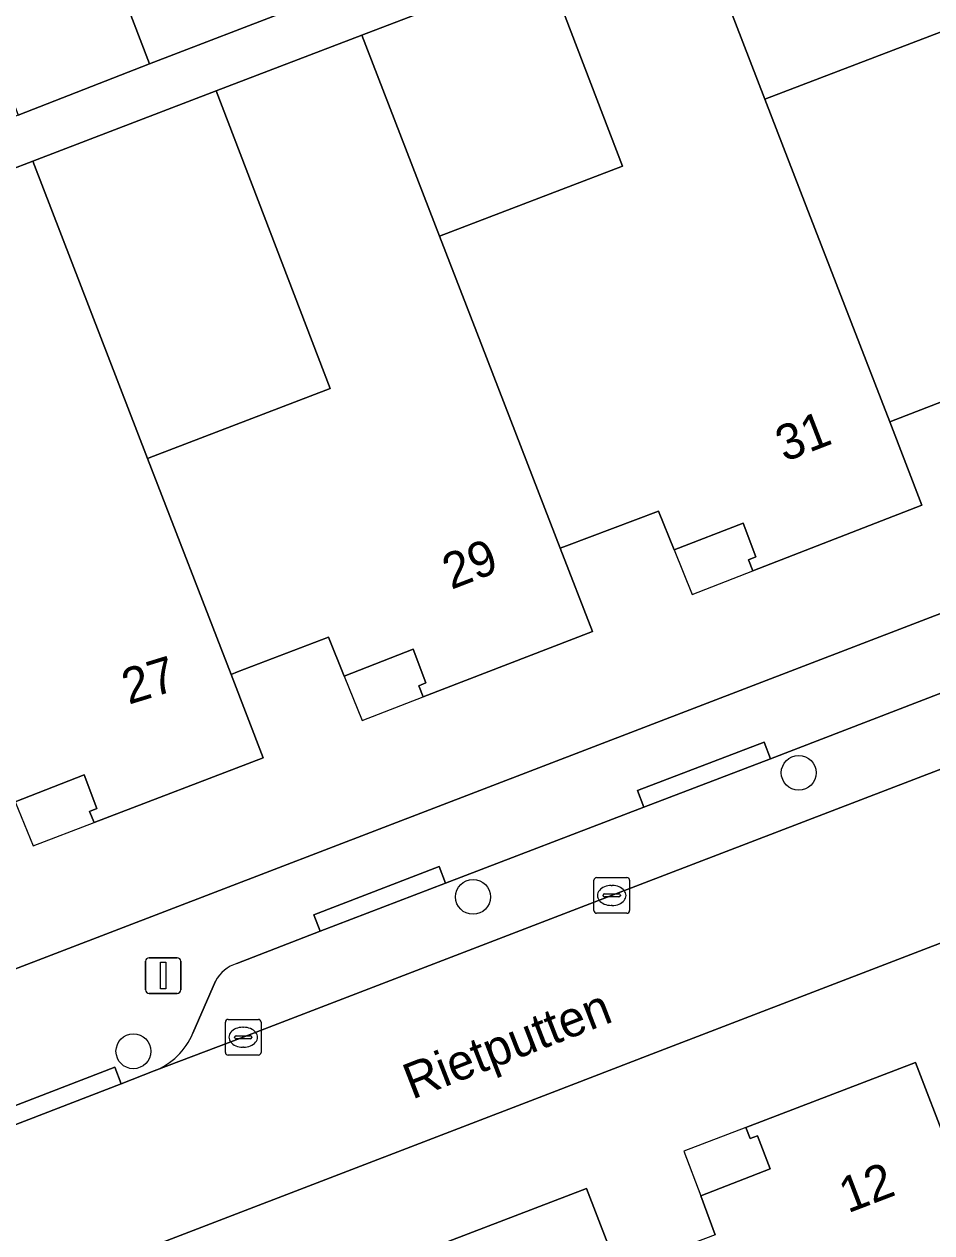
# Model space of a CAD drawing. Extents: x 159262 to 160143, y 383399 to 384319.
# Drawn here: x 159446.11 to 159471.6, y 383678.39 to 383712.34 of the extents above; entities that cross this region are included whole.
import ezdxf

# ---------------------------------------------------------------- set-up
doc = ezdxf.new("R2010")
doc.units = 0
for name, color, linetype in [('IMGEO_Boom', 7, 'Continuous'), ('IMGEO_Erf', 7, 'Continuous'), ('IMGEO_Kolk', 7, 'Continuous'), ('IMGEO_Lichtmast', 7, 'Continuous'), ('IMGEO_Openbare_ruimte_label', 7, 'Continuous'), ('IMGEO_Pand', 7, 'Continuous'), ('IMGEO_Pand_nummerreeks', 7, 'Continuous'), ('IMGEO_Pand_overbouw', 7, 'Continuous'), ('IMGEO_Parkeervlak_open', 7, 'Continuous'), ('IMGEO_Rijbaan_lokaal_open', 7, 'Continuous'), ('IMGEO_Voetpad_open', 7, 'Continuous')]:
    doc.layers.add(name, color=color, linetype=linetype)

msp = doc.modelspace()

# ---------------------------------------------------------------- linework, layer by layer
at = {"layer": 'IMGEO_Boom'}
for centre in [(159467.858, 383691.308), (159458.713, 383687.822), (159449.177, 383683.486)]:
    msp.add_circle(centre, 0.489, dxfattribs=at)
at = {"layer": 'IMGEO_Erf'}
for points in [[(159435.186, 383681.698), (159493.36, 383704.052), (159485.859, 383723.61)], [(159409.505, 383716.326), (159412.893, 383700.61), (159413.681, 383697.451), (159416.385, 383698.491), (159415.225, 383701.507), (159423.514, 383704.695), (159424.645, 383701.755), (159424.841, 383701.83), (159423.961, 383704.167), (159429.312, 383706.183), (159433.524, 383707.771), (159434.404, 383705.433), (159438.242, 383706.88), (159437.291, 383709.406), (159440.824, 383710.737), (159444.985, 383712.306), (159445.937, 383709.78), (159449.626, 383711.226), (159448.675, 383713.719)], [(159473.152, 383702.227), (159470.589, 383701.232), (159470.415, 383701.164), (159471.319, 383698.826), (159466.573, 383696.983), (159466.45, 383697.293), (159466.651, 383697.378), (159466.296, 383698.32), (159464.358, 383697.571), (159463.92, 383698.656), (159461.342, 383697.685), (159461.162, 383697.617), (159462.068, 383695.274), (159457.314, 383693.441), (159457.19, 383693.751), (159457.391, 383693.836), (159457.035, 383694.778), (159455.098, 383694.025), (159454.655, 383695.118), (159452.104, 383694.141), (159451.92, 383694.07), (159452.823, 383691.731), (159448.071, 383689.911), (159447.947, 383690.221), (159448.148, 383690.306), (159447.792, 383691.248), (159445.855, 383690.495)], [(159465.512, 383678.331), (159465.105, 383679.423), (159467.053, 383680.18), (159466.7, 383681.111), (159466.491, 383681.039), (159466.372, 383681.346), (159471.14, 383683.17), (159472.047, 383680.807), (159472.221, 383680.874), (159474.8, 383681.86), (159474.376, 383682.968), (159476.324, 383683.725), (159475.971, 383684.656), (159475.762, 383684.584), (159475.643, 383684.891), (159480.379, 383686.689), (159480.557, 383686.757), (159480.521, 383686.858), (159480.656, 383686.909), (159482.084, 383690.461), (159463.605, 383683.356), (159461.057, 383682.377), (159448.102, 383677.396)], [(159457.135, 383677.806), (159461.898, 383679.632), (159462.795, 383677.296)]]:
    msp.add_lwpolyline(points, dxfattribs=at)
for points in [[(159470, 383717.549), (159464.844, 383715.573), (159466.909, 383710.231), (159472.05, 383712.2)], [(159460.746, 383714.002), (159455.588, 383712.026), (159457.772, 383706.379), (159462.913, 383708.349)], [(159451.502, 383710.46), (159446.353, 383708.486), (159449.577, 383700.137), (159449.737, 383700.198), (159454.705, 383702.103)]]:
    msp.add_lwpolyline(points, close=True, dxfattribs=at)
at = {"layer": 'IMGEO_Kolk'}
for p, q in [((159462.107, 383687.437), (159462.107, 383688.289)), ((159462.182, 383688.363), (159463.034, 383688.363)), ((159462.595, 383688.143), (159462.62, 383688.143)), ((159463.108, 383688.289), (159463.108, 383687.437)), ((159462.366, 383687.857), (159462.366, 383687.869)), ((159462.804, 383687.82), (159462.406, 383687.82)), ((159462.409, 383687.906), (159462.807, 383687.906)), ((159462.85, 383687.869), (159462.85, 383687.857)), ((159463.034, 383687.363), (159462.182, 383687.363)), ((159462.618, 383687.583), (159462.593, 383687.583)), ((159451.759, 383683.455), (159451.759, 383684.307)), ((159451.834, 383684.381), (159452.686, 383684.381)), ((159452.76, 383684.307), (159452.76, 383683.455)), ((159452.247, 383684.161), (159452.272, 383684.161)), ((159452.018, 383683.875), (159452.018, 383683.887)), ((159452.456, 383683.838), (159452.058, 383683.838)), ((159452.061, 383683.924), (159452.459, 383683.924)), ((159452.502, 383683.887), (159452.502, 383683.875)), ((159452.686, 383683.381), (159451.834, 383683.381)), ((159452.27, 383683.601), (159452.245, 383683.601))]:
    msp.add_line(p, q, dxfattribs=at)
for points in [[(159462.107, 383687.437), (159462.107, 383688.289)], [(159462.182, 383688.363), (159463.034, 383688.363)], [(159463.108, 383688.289), (159463.108, 383687.437)], [(159463.034, 383687.363), (159462.182, 383687.363)], [(159451.759, 383683.455), (159451.759, 383684.307)], [(159451.834, 383684.381), (159452.686, 383684.381)], [(159452.76, 383684.307), (159452.76, 383683.455)], [(159452.686, 383683.381), (159451.834, 383683.381)]]:
    msp.add_lwpolyline(points, dxfattribs=at)
for centre, radius, start, end in [((159462.184, 383688.287), 0.0765, 91.552, 178.448), ((159462.184, 383688.287), 0.0765, 91.552, 178.448), ((159463.032, 383688.287), 0.0765, 1.552, 88.448), ((159463.032, 383688.287), 0.0765, 1.552, 88.448), ((159462.406, 383687.866), 0.0403, 85.8775, 175.7526), ((159462.403, 383687.856), 0.0366, 178.938, 274.7102), ((159462.807, 383687.863), 0.043, 264.8664, 352.4533), ((159462.811, 383687.868), 0.0386, 1.7309, 96.639), ((159462.184, 383687.439), 0.0765, 181.552, 268.448), ((159462.184, 383687.439), 0.0765, 181.552, 268.448), ((159463.032, 383687.439), 0.0765, 271.552, 358.448), ((159463.032, 383687.439), 0.0765, 271.552, 358.448), ((159451.836, 383684.305), 0.0765, 91.552, 178.448), ((159451.836, 383684.305), 0.0765, 91.552, 178.448), ((159452.684, 383684.305), 0.0765, 1.552, 88.448), ((159452.684, 383684.305), 0.0765, 1.552, 88.448), ((159452.058, 383683.884), 0.0403, 85.8775, 175.7526), ((159452.055, 383683.874), 0.0366, 178.938, 274.7102), ((159452.459, 383683.881), 0.043, 264.8664, 352.4533), ((159452.463, 383683.886), 0.0386, 1.7309, 96.639), ((159451.836, 383683.457), 0.0765, 181.552, 268.448), ((159451.836, 383683.457), 0.0765, 181.552, 268.448), ((159452.684, 383683.457), 0.0765, 271.552, 358.448), ((159452.684, 383683.457), 0.0765, 271.552, 358.448)]:
    msp.add_arc(centre, radius, start, end, dxfattribs=at)
for centre, major_axis, ratio, start_param, end_param in [((159462.594, 383687.863), (-0.387, 0.002), 0.722429, 4.712389, 7.853982), ((159462.619, 383687.863), (-0.39, 0.002), 0.717154, 1.570796, 4.712389), ((159452.246, 383683.881), (-0.387, 0.002), 0.722429, 4.712389, 7.853982), ((159452.271, 383683.881), (-0.39, 0.002), 0.717154, 1.570796, 4.712389)]:
    msp.add_ellipse(centre, major_axis=major_axis, ratio=ratio, start_param=start_param, end_param=end_param, dxfattribs=at)
at = {"layer": 'IMGEO_Lichtmast'}
for p, q in [((159449.517, 383685.213), (159449.517, 383686.013)), ((159449.517, 383686.013), (159449.517, 383685.213)), ((159449.617, 383686.113), (159450.407, 383686.113)), ((159450.407, 383686.113), (159449.617, 383686.113)), ((159450.507, 383686.013), (159450.507, 383685.213)), ((159450.507, 383685.213), (159450.507, 383686.013)), ((159450.407, 383685.113), (159449.617, 383685.113)), ((159449.617, 383685.113), (159450.407, 383685.113))]:
    msp.add_line(p, q, dxfattribs=at)
msp.add_lwpolyline([(159449.937, 383685.988), (159450.087, 383685.988), (159450.087, 383685.238), (159449.937, 383685.238), (159449.937, 383685.988)], dxfattribs=at)
for centre, start, end in [((159449.617, 383686.013), 90, 180), ((159449.617, 383686.013), 90, 180), ((159450.407, 383686.013), 0, 90), ((159450.407, 383686.013), 360, 90), ((159449.617, 383685.213), 180, 270), ((159449.617, 383685.213), 180, 270), ((159450.407, 383685.213), 270, 0), ((159450.407, 383685.213), 270, 0)]:
    msp.add_arc(centre, 0.1, start, end, dxfattribs=at)
at = {"layer": 'IMGEO_Pand'}
for points in [[(159477.308, 383710.765), (159475.962, 383714.243), (159474.079, 383719.112), (159470, 383717.549), (159472.05, 383712.2), (159466.909, 383710.231), (159468.071, 383707.226), (159470.415, 383701.164), (159470.589, 383701.232), (159473.152, 383702.227), (159473.568, 383701.107), (159475.541, 383701.86), (159475.896, 383700.918), (159475.695, 383700.833), (159475.818, 383700.523), (159480.562, 383702.355), (159479.649, 383704.714)], [(159468.071, 383707.226), (159466.909, 383710.231), (159464.844, 383715.573), (159460.746, 383714.002), (159462.913, 383708.349), (159457.772, 383706.379), (159458.817, 383703.679), (159461.162, 383697.617), (159461.342, 383697.685), (159463.92, 383698.656), (159464.358, 383697.571), (159466.296, 383698.32), (159466.651, 383697.378), (159466.45, 383697.293), (159466.573, 383696.983), (159471.319, 383698.826), (159470.415, 383701.164)], [(159452.343, 383715.119), (159448.675, 383713.719), (159449.626, 383711.226), (159453.776, 383712.81), (159453.664, 383713.098), (159454.129, 383713.279), (159453.677, 383714.445), (159452.745, 383714.083)], [(159458.817, 383703.679), (159457.772, 383706.379), (159455.588, 383712.026), (159451.502, 383710.46), (159454.705, 383702.103), (159449.737, 383700.198), (159449.577, 383700.137), (159451.92, 383694.07), (159452.104, 383694.141), (159454.655, 383695.118), (159455.098, 383694.025), (159457.035, 383694.778), (159457.391, 383693.836), (159457.19, 383693.751), (159457.314, 383693.441), (159462.068, 383695.274), (159461.162, 383697.617)], [(159449.577, 383700.137), (159446.353, 383708.486), (159442.249, 383706.913), (159445.452, 383698.556), (159440.493, 383696.655), (159440.336, 383696.595), (159442.676, 383690.533), (159442.857, 383690.602), (159445.415, 383691.579), (159445.855, 383690.495), (159447.792, 383691.248), (159448.148, 383690.306), (159447.947, 383690.221), (159448.071, 383689.911), (159452.823, 383691.731), (159451.92, 383694.07)], [(159472.956, 383666.51), (159476.945, 383668.042), (159474.354, 383674.795), (159472.047, 383680.807), (159471.14, 383683.17), (159466.372, 383681.346), (159466.491, 383681.039), (159466.7, 383681.111), (159467.053, 383680.18), (159465.105, 383679.423), (159465.512, 383678.331), (159462.97, 383677.363), (159462.795, 383677.296), (159465.122, 383671.237), (159470.366, 383673.261)], [(159465.122, 383671.237), (159462.795, 383677.296), (159461.898, 383679.632), (159457.135, 383677.806), (159457.254, 383677.499), (159457.463, 383677.571), (159457.816, 383676.64), (159455.868, 383675.883), (159456.285, 383674.788), (159453.419, 383673.686), (159455.745, 383667.638), (159461.018, 383669.666), (159463.354, 383663.603), (159467.452, 383665.169)]]:
    msp.add_lwpolyline(points, close=True, dxfattribs=at)
at = {"layer": 'IMGEO_Pand_overbouw'}
for points in [[(159466.45, 383697.293), (159466.651, 383697.378), (159466.296, 383698.32), (159464.358, 383697.571), (159464.863, 383696.319), (159466.573, 383696.983)], [(159457.19, 383693.751), (159457.391, 383693.836), (159457.035, 383694.778), (159455.098, 383694.025), (159455.602, 383692.781), (159457.314, 383693.441)], [(159447.947, 383690.221), (159448.148, 383690.306), (159447.792, 383691.248), (159445.855, 383690.495), (159446.358, 383689.255), (159448.071, 383689.911)], [(159466.7, 383681.111), (159466.491, 383681.039), (159466.372, 383681.346), (159464.636, 383680.682), (159465.105, 383679.423), (159467.053, 383680.18)]]:
    msp.add_lwpolyline(points, close=True, dxfattribs=at)
at = {"layer": 'IMGEO_Parkeervlak_open'}
for points in [[(159491.351, 383701.026), (159485.759, 383698.879), (159482.208, 383697.516), (159476.194, 383695.194), (159472.673, 383693.859), (159467.064, 383691.7), (159463.51, 383690.342), (159457.943, 383688.206), (159454.425, 383686.856), (159452.083, 383685.953)], [(159449.756, 383682.936), (159452.257, 383683.88), (159462.604, 383687.862), (159478.091, 383693.809), (159491.215, 383698.835), (159494.712, 383700.222)], [(159451.48, 383685.453), (159450.847, 383683.993)]]:
    msp.add_lwpolyline(points, dxfattribs=at)
for centre, radius, start, end in [((159452.393, 383684.966), 1.034, 107.4168, 151.9134), ((159449.06, 383684.746), 1.94, 291.0419, 337.1445)]:
    msp.add_arc(centre, radius, start, end, dxfattribs=at)
at = {"layer": 'IMGEO_Rijbaan_lokaal_open'}
msp.add_lwpolyline([(159448.102, 383677.396), (159461.057, 383682.377), (159463.605, 383683.356), (159482.084, 383690.461), (159490.681, 383693.764), (159496.449, 383695.986), (159494.814, 383700.262), (159494.712, 383700.222), (159491.215, 383698.835), (159478.091, 383693.809), (159462.604, 383687.862), (159452.257, 383683.88), (159449.756, 383682.936), (159448.831, 383682.571), (159445.289, 383681.205), (159444.982, 383681.1), (159444.018, 383680.757)], dxfattribs=at)
at = {"layer": 'IMGEO_Voetpad_open'}
for points in [[(159453.776, 383712.81), (159449.626, 383711.226), (159445.937, 383709.78), (159442.267, 383708.397), (159438.242, 383706.88), (159434.404, 383705.433), (159430.683, 383704.031), (159424.841, 383701.83), (159424.645, 383701.755), (159424.674, 383701.679), (159416.385, 383698.491), (159413.681, 383697.451), (159413.994, 383696.095), (159426.583, 383700.81), (159432.997, 383703.367), (159437.112, 383704.944), (159442.249, 383706.913), (159446.353, 383708.486), (159451.502, 383710.46), (159455.588, 383712.026), (159460.746, 383714.002)], [(159494.712, 383700.222), (159494.814, 383700.262), (159493.36, 383704.052), (159435.186, 383681.698), (159438.358, 383677.117), (159452.08, 383641.511), (159454.327, 383641.533), (159452.549, 383646.165), (159452.098, 383647.346), (159451.632, 383647.167), (159450.288, 383650.672), (159450.754, 383650.851), (159448.581, 383656.463), (159448.114, 383656.286), (159446.775, 383659.801), (159447.242, 383659.978), (159446.781, 383661.13), (159444.874, 383666.015), (159444.406, 383665.841), (159443.094, 383669.355), (159443.562, 383669.529), (159442.38, 383672.543), (159441.61, 383674.649), (159440.667, 383674.211)], [(159452.083, 383685.953), (159454.425, 383686.856), (159454.246, 383687.322), (159457.764, 383688.672), (159457.943, 383688.206), (159463.51, 383690.342), (159463.332, 383690.809), (159466.886, 383692.167), (159467.064, 383691.7), (159472.673, 383693.859), (159472.491, 383694.324), (159476.016, 383695.661), (159476.194, 383695.194), (159482.208, 383697.516), (159482.029, 383697.982), (159485.58, 383699.345), (159485.759, 383698.879), (159491.351, 383701.026)], [(159450.847, 383683.993), (159451.48, 383685.453)], [(159444.633, 383682.08), (159444.982, 383681.1), (159445.289, 383681.205), (159445.11, 383681.671), (159448.652, 383683.037), (159448.831, 383682.571), (159449.756, 383682.936)]]:
    msp.add_lwpolyline(points, dxfattribs=at)
for points in [[(159463.51, 383690.342), (159467.064, 383691.7), (159466.886, 383692.167), (159463.332, 383690.809)], [(159454.425, 383686.856), (159457.943, 383688.206), (159457.764, 383688.672), (159454.246, 383687.322)], [(159445.289, 383681.205), (159448.831, 383682.571), (159448.652, 383683.037), (159445.11, 383681.671)]]:
    msp.add_lwpolyline(points, close=True, dxfattribs=at)
for centre, radius, start, end in [((159452.393, 383684.966), 1.034, 107.4168, 151.9134), ((159449.06, 383684.746), 1.94, 291.0419, 337.1445)]:
    msp.add_arc(centre, radius, start, end, dxfattribs=at)

# ---------------------------------------------------------------- texts
at = {"layer": 'IMGEO_Openbare_ruimte_label'}
msp.add_text('Rietputten', height=1, rotation=21.2268, dxfattribs=at).set_placement((159457.004, 383682.125))
at = {"layer": 'IMGEO_Pand_nummerreeks'}
for s, rotation, p in [('31', 21.2224, (159467.458, 383700.029)), ('29', 21.0848, (159458.101, 383696.445)), ('27', 17.1028, (159449.044, 383693.218)), ('12', 20.9359, (159469.238, 383678.931))]:
    msp.add_text(s, height=1, rotation=rotation, dxfattribs=at).set_placement(p)

doc.saveas('drawing.dxf')
